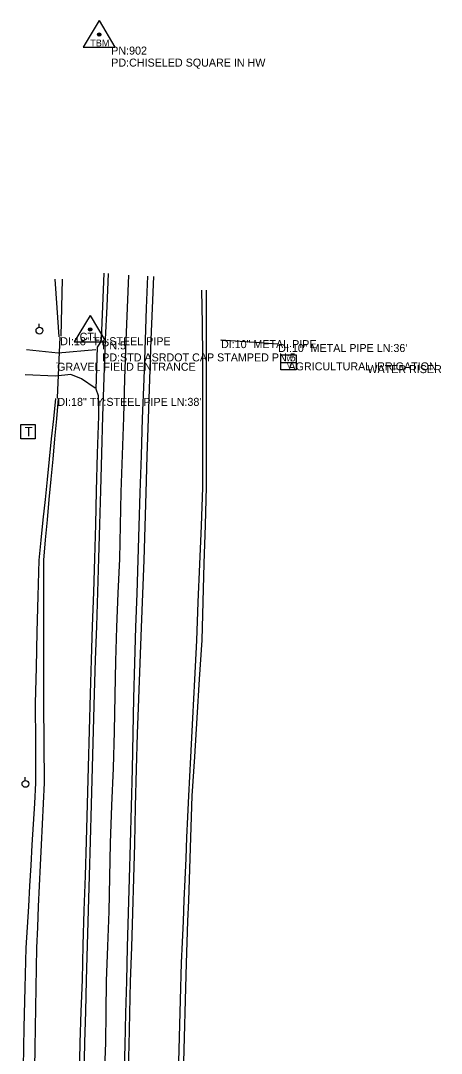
# Model space of a CAD drawing. Extents: x 1445297 to 1476720, y 2042269 to 2057889.
# Drawn here: x 1446076 to 1446338, y 2045155 to 2045800 of the extents above; entities that cross this region are included whole.
import ezdxf

# ---------------------------------------------------------------- set-up
doc = ezdxf.new("R2010")
doc.units = 0
for name, color, linetype in [('S_DITCHLINE', 7, 'Continuous'), ('S_DRG_PT_SYM', 7, 'Continuous'), ('S_DRIVEWAY', 7, 'Continuous'), ('S_EDGE_PAVEMENT', 7, 'Continuous'), ('S_MISC_STRUCTURES_ANNOT', 7, 'Continuous'), ('S_MSC_PT_SYM', 7, 'Continuous'), ('S_PAVEMENT_CROWN', 7, 'Continuous'), ('S_PRIMARY_CTL', 7, 'Continuous'), ('S_PRIMARY_CTL_ANNOT', 7, 'Continuous'), ('S_SHOULDER', 7, 'Continuous'), ('S_SIDE_DRAIN', 7, 'Continuous'), ('S_SIDE_DRAIN_ANNOT', 7, 'Continuous'), ('S_SURVEY_TEXT_ANNOT', 7, 'Continuous'), ('S_TELEPHONE_UTILITIES', 7, 'Continuous'), ('S_UTILITY_POLE', 7, 'Continuous'), ('S_WATER_UTILITIES', 7, 'Continuous'), ('S_WATER_UTILITIES_ANNOT', 7, 'Continuous')]:
    doc.layers.add(name, color=color, linetype=linetype)

msp = doc.modelspace()

# ---------------------------------------------------------------- linework, layer by layer
at = {"layer": 'S_DITCHLINE'}
for points in [[(1446099.78, 2045602.93), (1446098.54, 2045620.92), (1446097.31, 2045638.9)], [(1446101.05, 2045603.34), (1446101.46, 2045621.11), (1446101.86, 2045638.88)], [(1446174.22, 2045142.36), (1446174.88, 2045165.56), (1446175.55, 2045188.75), (1446176.22, 2045211.95), (1446176.78, 2045224.98), (1446177.34, 2045238.02), (1446177.9, 2045251.05), (1446178.46, 2045264.08), (1446179.02, 2045277.12), (1446179.58, 2045290.15), (1446180.14, 2045303.18), (1446180.7, 2045316.22), (1446181.94, 2045340.46), (1446183.18, 2045364.71), (1446184.42, 2045388.96), (1446185.66, 2045413.2), (1446186.63, 2045437.1), (1446187.6, 2045461.01), (1446188.56, 2045484.91), (1446189.53, 2045508.81), (1446189.51, 2045529.09), (1446189.48, 2045549.37), (1446189.46, 2045569.65), (1446189.44, 2045589.93), (1446189.18, 2045610.96), (1446188.92, 2045632)], [(1446177.41, 2045142.16), (1446178.04, 2045165.38), (1446178.67, 2045188.59), (1446179.31, 2045211.81), (1446179.75, 2045224.87), (1446180.19, 2045237.93), (1446180.64, 2045250.99), (1446181.08, 2045264.05), (1446181.53, 2045277.11), (1446181.97, 2045290.17), (1446182.42, 2045303.23), (1446182.86, 2045316.29), (1446184.38, 2045340.6), (1446185.9, 2045364.91), (1446187.43, 2045389.22), (1446188.95, 2045413.54), (1446189.66, 2045437.44), (1446190.36, 2045461.35), (1446191.07, 2045485.25), (1446191.78, 2045509.15), (1446191.79, 2045529.37), (1446191.8, 2045549.58), (1446191.81, 2045569.8), (1446191.82, 2045590.01), (1446191.76, 2045611.05), (1446191.7, 2045632.09)], [(1446077.47, 2045146.56), (1446078.08, 2045171.52), (1446078.7, 2045196.47), (1446079.31, 2045221.43), (1446080.06, 2045234.28), (1446080.81, 2045247.14), (1446081.56, 2045260), (1446082.31, 2045272.85), (1446083.05, 2045285.71), (1446083.8, 2045298.57), (1446084.55, 2045311.42), (1446085.3, 2045324.28), (1446085.18, 2045349.16), (1446085.07, 2045374.04), (1446085.63, 2045396.37), (1446086.19, 2045418.7), (1446086.75, 2045441.03), (1446087.32, 2045463.36), (1446088.62, 2045475.99), (1446089.91, 2045488.62), (1446091.21, 2045501.25), (1446092.51, 2045513.88), (1446093.81, 2045526.51), (1446095.11, 2045539.14), (1446096.41, 2045551.78), (1446097.7, 2045564.41)], [(1446084.6, 2045146.3), (1446084.8, 2045158.81), (1446085.01, 2045171.31), (1446085.22, 2045183.82), (1446085.42, 2045196.33), (1446085.63, 2045208.84), (1446085.84, 2045221.34), (1446086.43, 2045234.23), (1446087.03, 2045247.11), (1446087.62, 2045259.99), (1446088.22, 2045272.88), (1446088.81, 2045285.76), (1446089.41, 2045298.64), (1446090, 2045311.53), (1446090.6, 2045324.41), (1446090.43, 2045349.2), (1446090.27, 2045373.98), (1446090.24, 2045396.36), (1446090.22, 2045418.73), (1446090.19, 2045441.1), (1446090.16, 2045463.48), (1446091.33, 2045476.09), (1446092.5, 2045488.69), (1446093.66, 2045501.3), (1446094.83, 2045513.91), (1446095.99, 2045526.51), (1446097.16, 2045539.12), (1446098.33, 2045551.73), (1446099.49, 2045564.34)]]:
    msp.add_lwpolyline(points, dxfattribs=at)
at = {"layer": 'S_DRG_PT_SYM'}
for points in [[(1446100.48, 2045602.65), (1446100.48, 2045602.7), (1446100.48, 2045602.65), (1446100.43, 2045602.65), (1446100.48, 2045602.65), (1446100.48, 2045602.6), (1446100.48, 2045602.65), (1446100.53, 2045602.65)], [(1446200.82, 2045600.82), (1446200.82, 2045600.87), (1446200.82, 2045600.82), (1446200.77, 2045600.82), (1446200.82, 2045600.82), (1446200.82, 2045600.77), (1446200.82, 2045600.82), (1446200.87, 2045600.82)], [(1446236.51, 2045598.4), (1446236.51, 2045598.45), (1446236.51, 2045598.4), (1446236.46, 2045598.4), (1446236.51, 2045598.4), (1446236.51, 2045598.35), (1446236.51, 2045598.4), (1446236.56, 2045598.4)], [(1446098.7, 2045564.77), (1446098.7, 2045564.82), (1446098.7, 2045564.77), (1446098.65, 2045564.77), (1446098.7, 2045564.77), (1446098.7, 2045564.72), (1446098.7, 2045564.77), (1446098.75, 2045564.77)]]:
    msp.add_lwpolyline(points, dxfattribs=at)
at = {"layer": 'S_DRIVEWAY'}
for points in [[(1446079.46, 2045595.04), (1446099.17, 2045592.96), (1446122.76, 2045594.97)], [(1446122.19, 2045570.93), (1446113.78, 2045576.58), (1446107.15, 2045579.28), (1446097.5, 2045578.27), (1446078.58, 2045579.23)]]:
    msp.add_lwpolyline(points, dxfattribs=at)
at = {"layer": 'S_EDGE_PAVEMENT'}
for points in [[(1446115.39, 2045140.74), (1446115.92, 2045162.21), (1446116.44, 2045181.66), (1446116.96, 2045201.11), (1446117.57, 2045222.97), (1446118.17, 2045244.82), (1446118.8, 2045266.35), (1446119.43, 2045287.87), (1446120.05, 2045310.95), (1446120.66, 2045334.02), (1446121.27, 2045357.06), (1446121.88, 2045380.11), (1446122.55, 2045401.18), (1446123.23, 2045422.25), (1446123.86, 2045443.46), (1446124.49, 2045464.67), (1446125.13, 2045485.75), (1446125.77, 2045506.83), (1446126.46, 2045530.12), (1446127.14, 2045553.41), (1446127.98, 2045577.45), (1446128.81, 2045601.48), (1446129.7, 2045621.91), (1446130.59, 2045642.33)], [(1446140.3, 2045139.21), (1446140.91, 2045160.63), (1446141.47, 2045180.6), (1446142.04, 2045200.57), (1446142.56, 2045221.87), (1446143.08, 2045243.17), (1446143.72, 2045264.69), (1446144.37, 2045286.2), (1446144.95, 2045309.57), (1446145.53, 2045332.94), (1446145.96, 2045355.11), (1446146.4, 2045377.28), (1446147.04, 2045399.4), (1446147.68, 2045421.52), (1446148.41, 2045442.59), (1446149.14, 2045463.65), (1446149.8, 2045484.57), (1446150.46, 2045505.49), (1446151.17, 2045528.71), (1446151.88, 2045551.94), (1446152.77, 2045576.42), (1446153.67, 2045600.91), (1446154.39, 2045620.83), (1446155.1, 2045640.75)]]:
    msp.add_lwpolyline(points, dxfattribs=at)
at = {"layer": 'S_MSC_PT_SYM'}
for points in [[(1446098.49, 2045586.7), (1446098.49, 2045586.75), (1446098.49, 2045586.7), (1446098.44, 2045586.7), (1446098.49, 2045586.7), (1446098.49, 2045586.65), (1446098.49, 2045586.7), (1446098.54, 2045586.7)], [(1446292.16, 2045585.22), (1446292.16, 2045585.27), (1446292.16, 2045585.22), (1446292.11, 2045585.22), (1446292.16, 2045585.22), (1446292.16, 2045585.17), (1446292.16, 2045585.22), (1446292.21, 2045585.22)]]:
    msp.add_lwpolyline(points, dxfattribs=at)
at = {"layer": 'S_PAVEMENT_CROWN'}
msp.add_lwpolyline([(1446128.16, 2045140.5), (1446128.89, 2045161.96), (1446129.08, 2045181.26), (1446129.27, 2045200.55), (1446130.13, 2045222.31), (1446130.99, 2045244.07), (1446131.43, 2045265.44), (1446131.86, 2045286.81), (1446132.78, 2045310.19), (1446133.69, 2045333.56), (1446134.25, 2045356.37), (1446134.82, 2045379.18), (1446135.26, 2045400.38), (1446135.71, 2045421.58), (1446136.66, 2045442.92), (1446137.61, 2045464.26), (1446138.08, 2045485.11), (1446138.55, 2045505.96), (1446139.33, 2045529.26), (1446140.11, 2045552.57), (1446140.9, 2045576.56), (1446141.68, 2045600.56), (1446142.44, 2045620.95), (1446143.19, 2045641.34)], dxfattribs=at)
at = {"layer": 'S_PRIMARY_CTL'}
for p, q in [((1446124.81, 2045800.32), (1446114.77, 2045783.8)), ((1446124.81, 2045800.32), (1446134.63, 2045783.8)), ((1446114.77, 2045783.8), (1446134.63, 2045783.8)), ((1446119.17, 2045616.24), (1446109.14, 2045599.73)), ((1446119.17, 2045616.24), (1446128.99, 2045599.73)), ((1446109.14, 2045599.73), (1446128.99, 2045599.73))]:
    msp.add_line(p, q, dxfattribs=at)
for centre, radius in [((1446124.81, 2045791.62), 1.04), ((1446124.81, 2045791.62), 0.609), ((1446124.81, 2045791.62), 0.344), ((1446119.17, 2045607.54), 1.04), ((1446119.17, 2045607.54), 0.609), ((1446119.17, 2045607.54), 0.344)]:
    msp.add_circle(centre, radius, dxfattribs=at)
at = {"layer": 'S_SHOULDER'}
for points in [[(1446112.44, 2045140.66), (1446112.93, 2045161.93), (1446113.61, 2045181.69), (1446114.29, 2045201.44), (1446114.87, 2045223.06), (1446115.46, 2045244.67), (1446116.18, 2045266.35), (1446116.89, 2045288.02), (1446117.51, 2045311.06), (1446118.13, 2045334.1), (1446118.71, 2045356.99), (1446119.29, 2045379.87), (1446119.97, 2045401.09), (1446120.66, 2045422.3), (1446121.37, 2045443.4), (1446122.09, 2045464.49), (1446122.62, 2045485.61), (1446123.16, 2045506.72), (1446123.83, 2045530.06), (1446124.5, 2045553.4), (1446124.41, 2045565.98), (1446122.91, 2045570.17), (1446123.32, 2045583.31), (1446123.72, 2045596.45), (1446125.35, 2045598.95), (1446126.23, 2045601.54), (1446127.06, 2045622.06), (1446127.9, 2045642.58)], [(1446142.91, 2045139.1), (1446143.51, 2045160.46), (1446143.97, 2045180.44), (1446144.43, 2045200.42), (1446145.07, 2045221.86), (1446145.7, 2045243.31), (1446146.37, 2045264.8), (1446147.03, 2045286.3), (1446147.53, 2045309.66), (1446148.03, 2045333.01), (1446148.78, 2045354.89), (1446149.52, 2045376.76), (1446150.33, 2045399.1), (1446151.14, 2045421.45), (1446151.97, 2045442.42), (1446152.79, 2045463.39), (1446153.42, 2045484.39), (1446154.04, 2045505.39), (1446154.82, 2045528.58), (1446155.61, 2045551.78), (1446156.42, 2045576.45), (1446157.24, 2045601.12), (1446158.02, 2045620.79), (1446158.8, 2045640.46)]]:
    msp.add_lwpolyline(points, dxfattribs=at)
at = {"layer": 'S_SIDE_DRAIN'}
for p, q in [((1446098.7, 2045564.77), (1446100.48, 2045602.65)), ((1446236.51, 2045598.4), (1446200.82, 2045600.82))]:
    msp.add_line(p, q, dxfattribs=at)
at = {"layer": 'S_TELEPHONE_UTILITIES'}
msp.add_lwpolyline([(1446075.8, 2045539.15), (1446075.8, 2045548.15), (1446084.8, 2045548.15), (1446084.8, 2045539.15)], close=True, dxfattribs=at)
at = {"layer": 'S_UTILITY_POLE'}
for p, q in [((1446087.4, 2045608.92), (1446087.4, 2045611.03)), ((1446078.65, 2045325.88), (1446078.65, 2045327.99))]:
    msp.add_line(p, q, dxfattribs=at)
for centre in [(1446087.52, 2045606.78), (1446078.77, 2045323.74)]:
    msp.add_circle(centre, 2.13, dxfattribs=at)
at = {"layer": 'S_WATER_UTILITIES'}
for p, q in [((1446238.2, 2045591.64), (1446247.61, 2045591.64)), ((1446238.2, 2045582.22), (1446238.2, 2045591.64)), ((1446238.2, 2045586.95), (1446247.61, 2045586.95)), ((1446247.61, 2045591.64), (1446247.61, 2045582.22)), ((1446247.61, 2045582.22), (1446238.2, 2045582.22))]:
    msp.add_line(p, q, dxfattribs=at)

# ---------------------------------------------------------------- texts
at = {"layer": 'S_MISC_STRUCTURES_ANNOT'}
msp.add_text('WATER RISER', height=5, dxfattribs=at).set_placement((1446292.16, 2045580.22))
at = {"layer": 'S_PRIMARY_CTL'}
for s, height, p in [('TBM', 4.287, (1446119.16, 2045784.23)), ('CTL', 5, (1446112.58, 2045600.47))]:
    msp.add_text(s, height=height, dxfattribs=at).set_placement(p)
at = {"layer": 'S_PRIMARY_CTL_ANNOT'}
for s, p in [('PN:902', (1446132.31, 2045779.12)), ('PD:CHISELED SQUARE IN HW', (1446132.31, 2045771.62)), ('PN:5', (1446126.67, 2045595.04)), ('PD:STD ASRDOT CAP STAMPED PN:5', (1446126.67, 2045587.54))]:
    msp.add_text(s, height=5, dxfattribs=at).set_placement(p)
at = {"layer": 'S_SIDE_DRAIN_ANNOT'}
for s, p in [('DI:18" TY:STEEL PIPE', (1446100.48, 2045597.65)), ('DI:10" METAL PIPE', (1446200.82, 2045595.82)), ('DI:10" METAL PIPE LN:36\'', (1446236.51, 2045593.4)), ('DI:18" TY:STEEL PIPE LN:38\'', (1446098.7, 2045559.77))]:
    msp.add_text(s, height=5, dxfattribs=at).set_placement(p)
at = {"layer": 'S_SURVEY_TEXT_ANNOT'}
msp.add_text('GRAVEL FIELD ENTRANCE', height=5, dxfattribs=at).set_placement((1446098.49, 2045581.7))
at = {"layer": 'S_TELEPHONE_UTILITIES'}
msp.add_text('T', height=6, dxfattribs=at).set_placement((1446078.36, 2045540.65))
at = {"layer": 'S_WATER_UTILITIES'}
for s, p in [('W', (1446241.75, 2045587.48)), ('V', (1446241.99, 2045583.42))]:
    msp.add_text(s, height=3, dxfattribs=at).set_placement(p)
at = {"layer": 'S_WATER_UTILITIES_ANNOT'}
msp.add_text('AGRICULTURAL IRRIGATION', height=5, dxfattribs=at).set_placement((1446242.91, 2045581.95))

doc.saveas('drawing.dxf')
